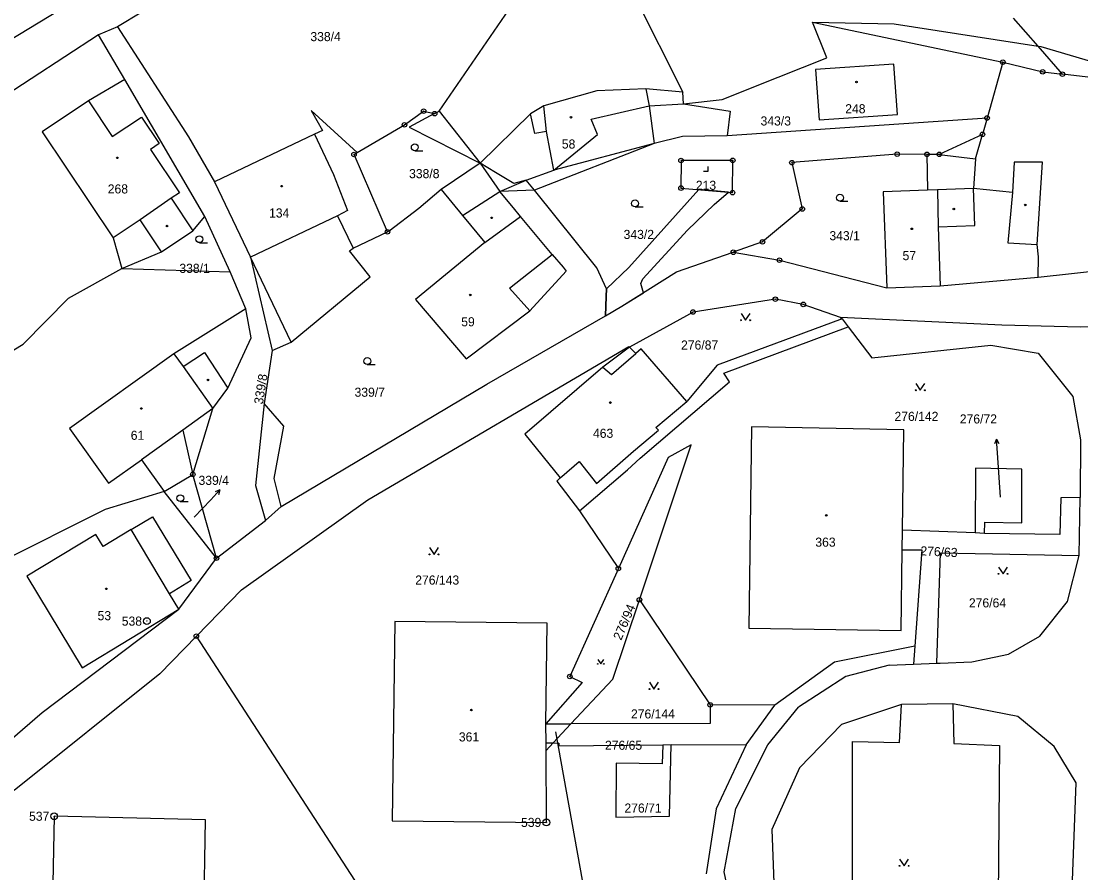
# Model space of a CAD drawing. Extents: x -745926 to -742978, y -968282 to -965689.
# Drawn here: x -744972.9 to -744856.3, y -966819.1 to -966725.4 of the extents above; entities that cross this region are included whole.
import ezdxf

# ---------------------------------------------------------------- set-up
doc = ezdxf.new("R2010")
doc.units = 0
for name, color, linetype in [('Hranice parcel', 7, 'Continuous'), ('Parcelní čísla', 7, 'Continuous'), ('Pop  PČ popisy', 7, 'Continuous'), ('Vnitřní kresba', 7, 'Continuous'), ('Věcná břemena k části', 7, 'Continuous'), ('Značky bodu BP', 7, 'Continuous'), ('Značky budov', 7, 'Continuous'), ('Značky kultur', 7, 'Continuous')]:
    doc.layers.add(name, color=color, linetype=linetype)

msp = doc.modelspace()

# ---------------------------------------------------------------- linework, layer by layer
at = {"layer": 'Hranice parcel'}
for p, q in [((-744917.15, -966699.46), (-744900.1, -966733.23)), ((-744924.57, -966703.11), (-744962.31, -966726.05)), ((-744946.43, -966710.72), (-744977.68, -966729.66)), ((-744861.01, -966728.18), (-744863.71, -966725.09)), ((-744962.31, -966726.05), (-744964.4, -966726.95)), ((-744964.4, -966726.95), (-744992.64, -966745.31)), ((-744961.52, -966731.86), (-744964.4, -966726.95)), ((-744858.33, -966731.26), (-744861.01, -966728.18)), ((-744864.89, -966729.94), (-744866.62, -966736.09)), ((-744952.72, -966746.93), (-744961.52, -966731.86)), ((-744845.2, -966732.8), (-744858.33, -966731.26)), ((-744900.03, -966734.52), (-744900.1, -966733.23)), ((-744927.42, -966735.61), (-744930.22, -966737.09)), ((-744928.63, -966735.33), (-744927.42, -966735.61)), ((-744866.62, -966736.09), (-744895.24, -966738.06)), ((-744866.62, -966736.09), (-744867.12, -966737.89)), ((-744930.22, -966737.09), (-744922.4, -966741.05)), ((-744867.12, -966737.89), (-744871.88, -966740.09)), ((-744903.25, -966738.9), (-744916.41, -966744.04)), ((-744936.29, -966740.1), (-744935.94, -966739.89)), ((-744932.61, -966748.62), (-744936.29, -966740.1)), ((-744922.4, -966741.05), (-744926.7, -966743.97)), ((-744922.4, -966741.05), (-744920.25, -966744.18)), ((-744916.41, -966744.04), (-744920.25, -966744.18)), ((-744909.57, -966752.56), (-744916.41, -966744.04)), ((-744949.91, -966753), (-744952.72, -966746.93)), ((-744860.98, -966753.59), (-744846.88, -966752.06)), ((-744961.83, -966752.65), (-744949.91, -966753)), ((-744948.2, -966757.1), (-744949.91, -966753)), ((-744945.31, -966761.66), (-744946.18, -966767.5)), ((-744957.18, -966777.18), (-744954.03, -966775.3)), ((-744951.43, -966784.53), (-744954.03, -966775.3)), ((-744957.18, -966777.18), (-744963.69, -966779.18)), ((-744951.43, -966784.53), (-744957.18, -966777.18)), ((-744856.48, -966784.24), (-744856.37, -966777.85)), ((-744963.69, -966779.18), (-744985.45, -966790.05)), ((-744911.47, -966779.32), (-744907.2, -966785.66)), ((-744951.43, -966784.53), (-744946.04, -966780.38)), ((-744875.96, -966783.59), (-744875.92, -966781.44)), ((-744867.93, -966781.73), (-744875.92, -966781.44)), ((-744866.9, -966781.8), (-744867.93, -966781.73)), ((-744904.88, -966789.1), (-744897.09, -966800.66)), ((-744911.18, -966798.21), (-744915.19, -966802.76)), ((-744889.96, -966800.71), (-744897.09, -966800.66)), ((-744893.12, -966805.07), (-744889.96, -966800.71)), ((-744915.19, -966802.76), (-744912.41, -966802.77)), ((-744912.41, -966802.77), (-744914.36, -966804.85)), ((-744915.14, -966805.69), (-744914.36, -966804.85)), ((-744915.12, -966813.6), (-744915.14, -966805.69)), ((-744902.32, -966805.05), (-744901.4, -966805.03)), ((-744901.4, -966805.03), (-744893.12, -966805.07))]:
    msp.add_line(p, q, dxfattribs=at)
for points in [[(-744927.42, -966735.61), (-744926.93, -966735.35), (-744916.41, -966720.03), (-744924.57, -966703.11)], [(-744962.31, -966726.05), (-744954.52, -966738.17), (-744951.63, -966743.11)], [(-744900.03, -966734.52), (-744895.78, -966734.06), (-744889.61, -966731.6), (-744884.27, -966729.47), (-744885.82, -966725.54), (-744864.89, -966729.94)], [(-744885.11, -966736.29), (-744876.49, -966735.7), (-744876.87, -966730.16), (-744885.49, -966730.75), (-744885.11, -966736.29)], [(-744864.89, -966729.94), (-744860.5, -966731), (-744858.33, -966731.26)], [(-744961.52, -966731.86), (-744965.51, -966734.21), (-744970.59, -966737.6), (-744962.79, -966749.28), (-744961.83, -966752.65)], [(-744900.1, -966733.23), (-744904.19, -966732.89), (-744909.55, -966733.11), (-744915.4, -966734.76), (-744916.85, -966735.63), (-744922.4, -966741.05)], [(-744914.31, -966741.81), (-744909.49, -966737.91), (-744910.2, -966736.23), (-744903.79, -966734.74), (-744900.03, -966734.52)], [(-744935.94, -966739.89), (-744941.02, -966735.28), (-744939.74, -966737.45), (-744940.64, -966737.88), (-744951.63, -966743.11)], [(-744935.94, -966739.89), (-744930.74, -966736.84), (-744928.63, -966735.33)], [(-744895.24, -966738.06), (-744900.13, -966738.11), (-744903.25, -966738.9)], [(-744871.88, -966740.09), (-744873.24, -966740.09), (-744876.52, -966740.07), (-744888.1, -966741), (-744886.96, -966746.1), (-744891.34, -966749.72), (-744894.55, -966750.86)], [(-744894.61, -966740.75), (-744900.3, -966740.76), (-744900.31, -966743.8), (-744894.63, -966744.3), (-744894.61, -966740.75)], [(-744860.98, -966753.59), (-744860.97, -966751.35), (-744861.12, -966749.99), (-744860.52, -966740.95), (-744863.64, -966740.93), (-744863.81, -966744.29), (-744868.1, -966743.85), (-744872.06, -966743.99), (-744873.16, -966744.03), (-744878.04, -966744.21), (-744877.65, -966754.78)], [(-744920.25, -966744.18), (-744917.36, -966742.91), (-744914.31, -966741.81)], [(-744951.63, -966743.11), (-744947.68, -966751.41), (-744945.31, -966761.66)], [(-744926.7, -966743.97), (-744929.15, -966746.06), (-744932.42, -966748.53), (-744932.61, -966748.62)], [(-744926.7, -966743.97), (-744924.35, -966746.8), (-744921.88, -966749.77), (-744929.51, -966756.06), (-744923.94, -966762.57), (-744916.95, -966757.32)], [(-744914.47, -966751.09), (-744917.96, -966746.92), (-744918.74, -966745.99), (-744920.25, -966744.18)], [(-744992.64, -966745.31), (-744980.4, -966765.62), (-744972.7, -966760.99), (-744967.7, -966755.9), (-744961.83, -966752.65)], [(-744961.83, -966752.65), (-744957.48, -966750.8), (-744954.03, -966748.5), (-744952.72, -966746.93)], [(-744945.31, -966761.66), (-744943.22, -966760.75), (-744934.5, -966753.55), (-744936.8, -966750.7), (-744936.39, -966750.41), (-744932.61, -966748.62)], [(-744908.61, -966757.84), (-744906.82, -966756.81), (-744900.8, -966753.03), (-744894.55, -966750.86)], [(-744894.55, -966750.86), (-744889.47, -966751.73), (-744877.65, -966754.78)], [(-744916.95, -966757.32), (-744919.18, -966754.83), (-744914.47, -966751.09)], [(-744908.61, -966757.84), (-744908.54, -966755.72), (-744908.51, -966754.89), (-744909.57, -966752.56)], [(-744877.65, -966754.78), (-744871.77, -966754.57), (-744860.98, -966753.59)], [(-744882.74, -966758.04), (-744886.85, -966756.6), (-744889.92, -966756.03), (-744898.98, -966757.44), (-744905.96, -966761.32)], [(-744948.2, -966757.1), (-744956.12, -966762.04), (-744967.6, -966770.26), (-744963.29, -966776.27), (-744959.69, -966773.69), (-744957.18, -966777.18)], [(-744954.03, -966775.3), (-744951.82, -966768.05), (-744950.19, -966765.83), (-744947.6, -966760.27), (-744948.2, -966757.1)], [(-744946.04, -966780.38), (-744944.31, -966778.83), (-744921.67, -966765.38), (-744908.61, -966757.84)], [(-744911.47, -966779.32), (-744906.2, -966774.79), (-744904.8, -966773.52), (-744894.97, -966765.11), (-744895.59, -966764.17), (-744881.92, -966759.08)], [(-744882.74, -966758.04), (-744882.58, -966758.2), (-744881.92, -966759.08)], [(-744840.59, -966758.19), (-744841.68, -966758.23), (-744847.46, -966758.96), (-744856.34, -966759.09), (-744864.98, -966758.9), (-744882.74, -966758.04)], [(-744881.92, -966759.08), (-744879.29, -966762.49), (-744866.2, -966761.09), (-744861.01, -966761.98), (-744857.17, -966766.73), (-744856.35, -966771.5), (-744856.37, -966777.85)], [(-744953.64, -966793.11), (-744948.67, -966788.01), (-744934.78, -966778.1), (-744906.06, -966761.22), (-744905.96, -966761.32)], [(-744905.96, -966761.32), (-744908.89, -966763.49), (-744917.49, -966770.88), (-744913.6, -966775.67)], [(-744913.6, -966775.67), (-744913.43, -966775.54), (-744911.51, -966773.88), (-744909.59, -966776.32), (-744905.52, -966772.74), (-744902.78, -966770.43), (-744903.09, -966770.16), (-744899.65, -966767.3), (-744904.67, -966761.49), (-744905.27, -966762.01), (-744905.96, -966761.32)], [(-744946.18, -966767.5), (-744947.14, -966776.54), (-744946.04, -966780.38)], [(-744875.92, -966781.44), (-744875.79, -966770.39), (-744892.56, -966770.06), (-744892.83, -966792.23), (-744876.07, -966792.49), (-744875.96, -966783.59)], [(-744904.88, -966789.1), (-744899.17, -966772.05), (-744901.7, -966773.44), (-744907.2, -966785.66)], [(-744866.9, -966781.8), (-744866.85, -966780.56), (-744862.81, -966780.65), (-744862.8, -966774.72), (-744867.89, -966774.63), (-744867.93, -966781.73)], [(-744913.6, -966775.67), (-744913.97, -966776.04), (-744911.47, -966779.32)], [(-744856.37, -966777.85), (-744858.52, -966777.9), (-744858.6, -966781.91), (-744866.9, -966781.8)], [(-744964.71, -966781.92), (-744972.31, -966786.51), (-744966.22, -966796.6), (-744955.56, -966790.15), (-744956.59, -966788.43), (-744960.8, -966781.36), (-744963.91, -966783.24), (-744964.71, -966781.92)], [(-744974.13, -966804.56), (-744970.61, -966801.49), (-744955.56, -966790.15), (-744951.43, -966784.53)], [(-744875.96, -966783.59), (-744873.79, -966783.59), (-744874.56, -966794.2)], [(-744872.14, -966796.08), (-744871.76, -966783.94), (-744856.48, -966784.24)], [(-744872.14, -966796.08), (-744871.77, -966796.08), (-744868.28, -966795.93), (-744864.26, -966795.09), (-744860.8, -966793.11), (-744857.76, -966789.3), (-744856.48, -966784.24)], [(-744907.2, -966785.66), (-744912.54, -966797.55), (-744911.18, -966798.21)], [(-744912.41, -966802.77), (-744907.8, -966797.83), (-744904.88, -966789.1)], [(-744915.19, -966802.76), (-744915.04, -966791.69), (-744931.81, -966791.48), (-744932.08, -966813.43), (-744915.12, -966813.6)], [(-744953.64, -966793.11), (-744957.67, -966797.25), (-744973.68, -966810.09)], [(-744928.17, -966823.68), (-744934.84, -966822.06), (-744953.64, -966793.11)], [(-744874.56, -966794.2), (-744883.4, -966795.98), (-744889.96, -966800.71)], [(-744874.56, -966794.2), (-744874.7, -966796.19), (-744872.14, -966796.08)], [(-744897.09, -966800.66), (-744897.08, -966802.73), (-744912.41, -966802.77)], [(-744859.24, -966805.23), (-744863.22, -966801.93), (-744870.38, -966800.55), (-744876.04, -966800.63), (-744882.63, -966802.83), (-744887.28, -966807.6), (-744890.32, -966814.38), (-744889.96, -966823.16), (-744886.53, -966828.19), (-744881.82, -966831.74), (-744876.51, -966833.44), (-744870.65, -966833.24), (-744864.57, -966831.23), (-744860.78, -966828.65), (-744858.3, -966826.43), (-744857.36, -966823.88), (-744856.82, -966809.25), (-744859.24, -966805.23)], [(-744915.14, -966805.69), (-744915.13, -966804.83), (-744915.19, -966802.76)], [(-744914.36, -966804.85), (-744913.75, -966804.87), (-744913.76, -966805.17), (-744902.32, -966805.05)], [(-744902.32, -966805.05), (-744902.39, -966807.16), (-744907.44, -966807.08), (-744907.48, -966813.01), (-744901.56, -966812.9), (-744901.4, -966805.03)], [(-744893.12, -966805.07), (-744896.43, -966812.1), (-744897.52, -966819.26)], [(-744952.82, -966824.26), (-744952.63, -966813.33), (-744969.29, -966812.92), (-744969.74, -966835.07), (-744953.02, -966835.31), (-744952.86, -966826.31)]]:
    msp.add_lwpolyline(points, dxfattribs=at)
at = {"layer": 'Pop  PČ popisy'}
for p, q in [((-744865.59, -966771.43), (-744865.81, -966771.95)), ((-744865.49, -966772.93), (-744865.59, -966771.43)), ((-744865.59, -966771.43), (-744865.31, -966771.92)), ((-744865.14, -966777.8), (-744865.49, -966772.93)), ((-744952.06, -966778.12), (-744951.04, -966777.02)), ((-744951.04, -966777.02), (-744951.56, -966777.22)), ((-744951.04, -966777.02), (-744951.2, -966777.56)), ((-744953.87, -966780.02), (-744952.06, -966778.12)), ((-744914.12, -966803.64), (-744909.87, -966827.26))]:
    msp.add_line(p, q, dxfattribs=at)
at = {"layer": 'Vnitřní kresba'}
for p, q in [((-744904.19, -966732.89), (-744903.79, -966734.74)), ((-744965.51, -966734.21), (-744962.89, -966738.14)), ((-744900.03, -966734.52), (-744894.91, -966735.34)), ((-744926.93, -966735.35), (-744922.4, -966741.05)), ((-744916.38, -966737.8), (-744916.85, -966735.63)), ((-744915.1, -966737.56), (-744915.4, -966734.76)), ((-744903.79, -966734.74), (-744903.25, -966738.9)), ((-744894.91, -966735.34), (-744895.24, -966738.06)), ((-744962.89, -966738.14), (-744959.68, -966736)), ((-744959.68, -966736), (-744957.74, -966738.91)), ((-744940.64, -966737.88), (-744938.53, -966742.32)), ((-744915.1, -966737.56), (-744916.38, -966737.8)), ((-744914.31, -966741.81), (-744915.1, -966737.56)), ((-744867.88, -966740.59), (-744867.12, -966737.89)), ((-744957.74, -966738.91), (-744958.68, -966739.54)), ((-744903.25, -966738.9), (-744914.31, -966741.81)), ((-744958.68, -966739.54), (-744955.5, -966744.31)), ((-744873.24, -966740.09), (-744873.16, -966744.03)), ((-744871.88, -966740.09), (-744867.88, -966740.59)), ((-744920.72, -966742.1), (-744922.4, -966741.05)), ((-744867.88, -966740.59), (-744868.1, -966743.85)), ((-744938.53, -966742.32), (-744936.99, -966746.26)), ((-744918.69, -966743.31), (-744920.72, -966742.1)), ((-744917.36, -966742.91), (-744918.69, -966743.31)), ((-744916.41, -966744.04), (-744917.36, -966742.91)), ((-744867.95, -966747.91), (-744868.1, -966743.85)), ((-744956.41, -966744.92), (-744959.82, -966747.3)), ((-744955.5, -966744.31), (-744956.41, -966744.92)), ((-744956.41, -966744.92), (-744954.03, -966748.5)), ((-744924.35, -966746.8), (-744920.25, -966744.18)), ((-744872.06, -966743.99), (-744872.01, -966748.06)), ((-744863.81, -966744.29), (-744864.32, -966749.81)), ((-744959.82, -966747.3), (-744962.79, -966749.28)), ((-744957.48, -966750.8), (-744959.82, -966747.3)), ((-744938.09, -966746.84), (-744947.68, -966751.41)), ((-744936.99, -966746.26), (-744938.09, -966746.84)), ((-744938.09, -966746.84), (-744936.39, -966750.41)), ((-744921.88, -966749.77), (-744917.96, -966746.92)), ((-744872.01, -966748.06), (-744867.95, -966747.91)), ((-744872.01, -966748.06), (-744871.77, -966754.57)), ((-744864.32, -966749.81), (-744861.12, -966749.99)), ((-744943.22, -966760.75), (-744947.68, -966751.41)), ((-744916.95, -966757.32), (-744912.93, -966752.94)), ((-744882.58, -966758.2), (-744896.32, -966763.29)), ((-744956.12, -966762.04), (-744955.09, -966763.45)), ((-744955.09, -966763.45), (-744952.74, -966761.88)), ((-744952.74, -966761.88), (-744950.19, -966765.83)), ((-744907.97, -966764.33), (-744905.27, -966762.01)), ((-744955.09, -966763.45), (-744951.82, -966768.05)), ((-744908.89, -966763.49), (-744907.97, -966764.33)), ((-744896.32, -966763.29), (-744899.65, -966767.3)), ((-744951.82, -966768.05), (-744955.14, -966770.43)), ((-744944, -966770), (-744946.18, -966767.5)), ((-744955.14, -966770.43), (-744959.69, -966773.69)), ((-744955.14, -966770.43), (-744954.03, -966775.3)), ((-744945.06, -966775.75), (-744944, -966770)), ((-744944.31, -966778.83), (-744945.06, -966775.75)), ((-744960.8, -966781.36), (-744958.48, -966779.96)), ((-744958.48, -966779.96), (-744954.22, -966786.99)), ((-744954.22, -966786.99), (-744956.59, -966788.43)), ((-744877.39, -966796.31), (-744882.16, -966797.53)), ((-744877.39, -966796.31), (-744874.7, -966796.19)), ((-744882.16, -966797.53), (-744887.36, -966800.91)), ((-744890.75, -966805.08), (-744887.36, -966800.91)), ((-744876.25, -966804.82), (-744876.04, -966800.63)), ((-744870.38, -966800.55), (-744870.27, -966804.93)), ((-744915.13, -966804.83), (-744914.36, -966804.85)), ((-744894.27, -966812.08), (-744890.75, -966805.08)), ((-744881.46, -966829.33), (-744881.42, -966804.69)), ((-744881.42, -966804.69), (-744876.25, -966804.82)), ((-744870.27, -966804.93), (-744865.27, -966805.12)), ((-744865.27, -966805.12), (-744865.48, -966829.68)), ((-744895.57, -966819.03), (-744894.27, -966812.08)), ((-744894.14, -966825.43), (-744895.57, -966819.03))]:
    msp.add_line(p, q, dxfattribs=at)
for points in [[(-744885.82, -966725.54), (-744876.85, -966725.74), (-744861.01, -966728.18)], [(-744861.01, -966728.18), (-744860.69, -966728.22), (-744845.2, -966732.8)], [(-744914.47, -966751.09), (-744913.29, -966752.51), (-744912.93, -966752.94)]]:
    msp.add_lwpolyline(points, dxfattribs=at)
at = {"layer": 'Věcná břemena k části'}
msp.add_lwpolyline([(-744908.61, -966757.84), (-744906.82, -966756.81), (-744904.42, -966755.31), (-744904.71, -966754.31), (-744904.5, -966753.8), (-744899.58, -966748.42), (-744896.64, -966745.61), (-744895.06, -966744.26), (-744898.33, -966743.97), (-744906.03, -966752.53), (-744908.51, -966754.89), (-744908.54, -966755.72)], close=True, dxfattribs=at)
at = {"layer": 'Značky bodu BP'}
for centre, radius in [((-744864.89, -966729.94), 0.25), ((-744864.89, -966729.94), 0.0152), ((-744860.5, -966731), 0.25), ((-744860.5, -966731), 0.0152), ((-744858.33, -966731.26), 0.25), ((-744858.33, -966731.26), 0.0152), ((-744928.63, -966735.33), 0.25), ((-744928.63, -966735.33), 0.0152), ((-744927.42, -966735.61), 0.25), ((-744927.42, -966735.61), 0.0152), ((-744930.74, -966736.84), 0.25), ((-744930.74, -966736.84), 0.0152), ((-744866.62, -966736.09), 0.25), ((-744866.62, -966736.09), 0.0152), ((-744867.12, -966737.89), 0.25), ((-744867.12, -966737.89), 0.0152), ((-744936.29, -966740.1), 0.25), ((-744936.29, -966740.1), 0.0152), ((-744876.52, -966740.07), 0.25), ((-744876.52, -966740.07), 0.0152), ((-744873.24, -966740.09), 0.25), ((-744873.24, -966740.09), 0.0152), ((-744871.88, -966740.09), 0.25), ((-744871.88, -966740.09), 0.0152), ((-744900.3, -966740.76), 0.25), ((-744900.3, -966740.76), 0.0152), ((-744894.61, -966740.75), 0.25), ((-744894.61, -966740.75), 0.0152), ((-744888.1, -966741), 0.25), ((-744888.1, -966741), 0.0152), ((-744900.31, -966743.8), 0.25), ((-744900.31, -966743.8), 0.0152), ((-744894.63, -966744.3), 0.25), ((-744894.63, -966744.3), 0.0152), ((-744886.96, -966746.1), 0.25), ((-744886.96, -966746.1), 0.0152), ((-744932.61, -966748.62), 0.25), ((-744932.61, -966748.62), 0.0152), ((-744891.34, -966749.72), 0.25), ((-744891.34, -966749.72), 0.0152), ((-744894.55, -966750.86), 0.25), ((-744894.55, -966750.86), 0.0152), ((-744889.47, -966751.73), 0.25), ((-744889.47, -966751.73), 0.0152), ((-744889.92, -966756.03), 0.25), ((-744889.92, -966756.03), 0.0152), ((-744886.85, -966756.6), 0.25), ((-744886.85, -966756.6), 0.0152), ((-744898.98, -966757.44), 0.25), ((-744898.98, -966757.44), 0.0152), ((-744954.03, -966775.3), 0.25), ((-744954.03, -966775.3), 0.0152), ((-744951.43, -966784.53), 0.25), ((-744951.43, -966784.53), 0.0152), ((-744907.2, -966785.66), 0.25), ((-744907.2, -966785.66), 0.0152), ((-744904.88, -966789.1), 0.25), ((-744904.88, -966789.1), 0.0152), ((-744959.08, -966791.45), 0.375), ((-744959.08, -966791.45), 0.015), ((-744953.64, -966793.11), 0.25), ((-744953.64, -966793.11), 0.0152), ((-744912.54, -966797.55), 0.25), ((-744912.54, -966797.55), 0.0152), ((-744897.09, -966800.66), 0.25), ((-744897.09, -966800.66), 0.0152), ((-744969.29, -966812.92), 0.375), ((-744969.29, -966812.92), 0.015), ((-744915.12, -966813.6), 0.375), ((-744915.12, -966813.6), 0.015)]:
    msp.add_circle(centre, radius, dxfattribs=at)
at = {"layer": 'Značky budov'}
for centre in [(-744880.99, -966732.12), (-744912.42, -966736), (-744962.33, -966740.47), (-744944.26, -966743.59), (-744870.28, -966746.1), (-744862.41, -966745.66), (-744921.15, -966747.07), (-744956.87, -966747.98), (-744874.9, -966748.28), (-744923.49, -966755.56), (-744952.36, -966764.91), (-744959.7, -966768.05), (-744908.07, -966767.4), (-744884.32, -966779.81), (-744963.54, -966787.9), (-744923.37, -966801.24)]:
    msp.add_circle(centre, 0.0875, dxfattribs=at)
at = {"layer": 'Značky kultur'}
for p, q in [((-744929.6, -966739.69), (-744928.72, -966739.69)), ((-744897.31, -966741.93), (-744897.31, -966741.43)), ((-744897.81, -966741.93), (-744897.31, -966741.93)), ((-744905.36, -966745.86), (-744904.48, -966745.86)), ((-744882.81, -966745.24), (-744881.93, -966745.24)), ((-744953.31, -966749.81), (-744952.43, -966749.81)), ((-744934.83, -966763.21), (-744933.95, -966763.21)), ((-744955.41, -966778.3), (-744954.53, -966778.3))]:
    msp.add_line(p, q, dxfattribs=at)
for points in [[(-744893.7, -966757.6), (-744893.2, -966758.35), (-744892.7, -966757.6)], [(-744874.47, -966765.3), (-744873.97, -966766.05), (-744873.47, -966765.3)], [(-744927.98, -966783.36), (-744927.48, -966784.11), (-744926.98, -966783.36)], [(-744865.36, -966785.5), (-744864.86, -966786.25), (-744864.36, -966785.5)], [(-744909.47, -966795.66), (-744909.13, -966796.16), (-744908.8, -966795.66)], [(-744903.78, -966798.18), (-744903.28, -966798.93), (-744902.78, -966798.18)], [(-744876.25, -966817.63), (-744875.75, -966818.38), (-744875.25, -966817.63)]]:
    msp.add_lwpolyline(points, dxfattribs=at)
for centre, radius in [((-744929.6, -966739.31), 0.375), ((-744882.81, -966744.86), 0.375), ((-744905.36, -966745.48), 0.375), ((-744953.31, -966749.43), 0.375), ((-744893.7, -966758.35), 0.05), ((-744892.7, -966758.35), 0.05), ((-744934.83, -966762.83), 0.375), ((-744874.47, -966766.05), 0.05), ((-744873.47, -966766.05), 0.05), ((-744955.41, -966777.92), 0.375), ((-744927.98, -966784.11), 0.05), ((-744926.98, -966784.11), 0.05), ((-744865.36, -966786.25), 0.05), ((-744864.36, -966786.25), 0.05), ((-744909.47, -966796.16), 0.0335), ((-744908.8, -966796.16), 0.0335), ((-744903.78, -966798.93), 0.05), ((-744902.78, -966798.93), 0.05), ((-744876.25, -966818.38), 0.05), ((-744875.25, -966818.38), 0.05)]:
    msp.add_circle(centre, radius, dxfattribs=at)

# ---------------------------------------------------------------- texts
at = {"layer": 'Parcelní čísla'}
for s, p in [('338/4', (-744941.09, -966727.63)), ('248', (-744882.23, -966735.57)), ('343/3', (-744891.55, -966736.91)), ('58', (-744913.42, -966739.45)), ('338/8', (-744930.23, -966742.71)), ('268', (-744963.39, -966744.39)), ('213', (-744898.67, -966743.99)), ('134', (-744945.64, -966747.04)), ('343/2', (-744906.62, -966749.4)), ('343/1', (-744883.97, -966749.54)), ('57', (-744875.92, -966751.73)), ('338/1', (-744955.51, -966753.13)), ('59', (-744924.49, -966759.01)), ('276/87', (-744900.3, -966761.57)), ('339/7', (-744936.23, -966766.76)), ('276/142', (-744876.81, -966769.42)), ('276/72', (-744869.62, -966769.7)), ('61', (-744960.86, -966771.5)), ('463', (-744909.99, -966771.28)), ('339/4', (-744953.4, -966776.46)), ('363', (-744885.52, -966783.26)), ('276/143', (-744929.55, -966787.43)), ('276/64', (-744868.62, -966789.94)), ('53', (-744964.51, -966791.35)), ('276/144', (-744905.81, -966802.16)), ('361', (-744924.75, -966804.69)), ('276/65', (-744908.67, -966805.61)), ('276/71', (-744906.53, -966812.52))]:
    msp.add_text(s, height=1, dxfattribs=at).set_placement(p)
for s, rotation, p in [('339/8', 81, (-744946.32, -966767.64)), ('276/63', 357, (-744873.98, -966784.2)), ('276/94', 67, (-744906.89, -966793.63))]:
    msp.add_text(s, height=1, rotation=rotation, dxfattribs=at).set_placement(p)
at = {"layer": 'Značky bodu BP'}
for s, p in [('538', (-744961.85, -966791.95)), ('537', (-744972.05, -966813.42)), ('539', (-744917.91, -966814.1))]:
    msp.add_text(s, height=1, dxfattribs=at).set_placement(p)

doc.saveas('drawing.dxf')
